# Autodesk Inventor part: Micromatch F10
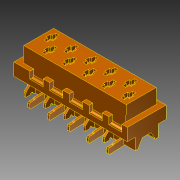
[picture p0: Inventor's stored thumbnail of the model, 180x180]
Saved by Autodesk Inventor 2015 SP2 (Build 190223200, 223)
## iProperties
Created: 2015-08
Part Number: Micromatch F10
Material: Allgemein
Document SubType Name: Modeling
Designer: rYan
Density: 1 g/cm^3
Appearance: Vorgabe
Author: workeradm
Title: c-1-188275-0-u-3d.igs
Organization: Unknown
Description: PTC IGES file: c-1-188275-0-u-3d.igs
Sending System: Pro/ENGINEER by Parametric Technology Corporation
Preprocessor: 2010430
Minimum Resolution: 0.001701
Sending System Product ID: C-1-188275-0
Receiving System Product ID: C-1-188275-0
Sent Units: Millimeter
Translation Standard: USPRO/IPO100 IGES 5.2
Author: rYan
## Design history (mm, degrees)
node "c-1-188275-0-u-3d1"
feature "Zusammengesetzt1"
node "Fläche1"
